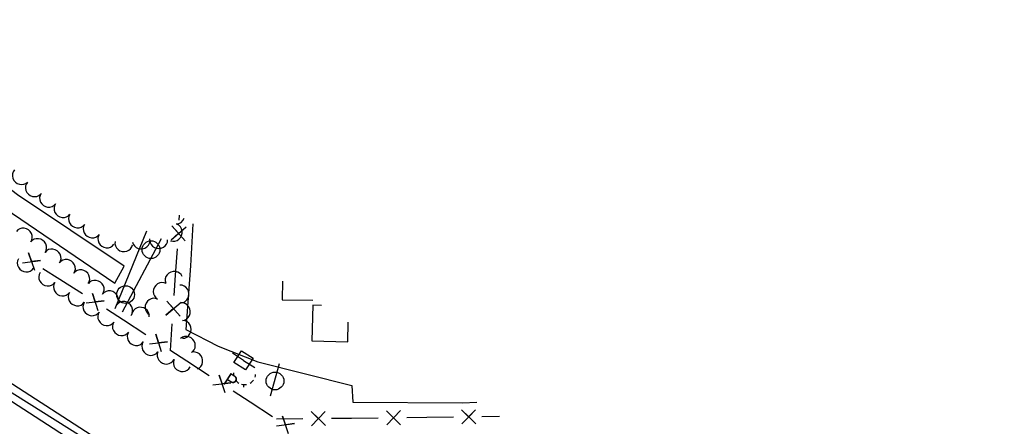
# Model space of a CAD drawing. Extents: x 1746010 to 1754829, y 655801 to 663091.
# Drawn here: x 1750940 to 1751497, y 659740 to 659969 of the extents above; entities that cross this region are included whole.
import ezdxf

# ---------------------------------------------------------------- set-up
doc = ezdxf.new("R2010")
doc.units = 0
for name, color, linetype in [('SURVEY - AERIAL SURVEY - Photo Control - Points - Elevations', 7, 'Continuous'), ('SURVEY - AERIAL SURVEY - Photo Control - Points - Locators', 7, 'Continuous'), ('SURVEY - AERIAL SURVEY - Photo Control with Text', 7, 'Continuous'), ('SURVEY - CENTERLINE - Existing Roads - Development', 7, 'Continuous'), ('SURVEY - CENTERLINE - Existing Roads Curve Text', 7, 'Continuous'), ('SURVEY - CENTERLINE - Existing Roads Text', 7, 'Continuous')]:
    doc.layers.add(name, color=color, linetype=linetype)

msp = doc.modelspace()

# ---------------------------------------------------------------- linework, layer by layer
at = {"layer": 'SURVEY - AERIAL SURVEY - Photo Control - Points - Elevations'}
msp.add_lwpolyline([(1751901.75, 659229.66), (1751903.78, 659232.49), (1751820.15, 659271.12), (1751720.09, 659319), (1751608.79, 659375.48), (1751511.86, 659425.67), (1751414.79, 659477.82), (1751309.42, 659535.79), (1751238.02, 659576.37), (1751119.98, 659647.33), (1751011.07, 659715.27), (1750920.63, 659773.68), (1750818.05, 659842.07), (1750688.97, 659930.51), (1750687.2, 659926.86)], dxfattribs=at)
at = {"layer": 'SURVEY - AERIAL SURVEY - Photo Control - Points - Locators'}
for points in [[(1751980.95, 659190.5), (1751865.03, 659241.97), (1751755.82, 659292.86), (1751627.46, 659356.04), (1751498.69, 659424), (1751376.94, 659489.68), (1751250.14, 659561.52), (1751113.15, 659643.48), (1750975.97, 659727.83), (1750858.05, 659804.33), (1750722.4, 659896.24), (1750620.83, 659969.19)], [(1750902.16, 659942.97), (1750902.94, 659927.48), (1750902.95, 659893.71), (1750903.13, 659886.46), (1750905.25, 659881.98), (1750918.24, 659872.14), (1750993.75, 659820.81), (1750998.91, 659830.33), (1750938.84, 659870.48), (1750930.13, 659877.33), (1750923.58, 659885.66), (1750919.37, 659891.98), (1750916.72, 659903.21), (1750915.86, 659929.32), (1750915.87, 659933.99)], [(1751981.66, 659195.26), (1751889.68, 659234.85), (1751784.21, 659284.64), (1751694.2, 659328.1), (1751603.81, 659373.71), (1751512.94, 659420.78), (1751440.06, 659459.77), (1751340.52, 659515.91), (1751224.32, 659581.45), (1751125.19, 659640.31), (1751025.2, 659702.76), (1750930.86, 659762.02), (1750841.47, 659821.93), (1750746.73, 659885.97), (1750687.69, 659926.53)], [(1751037.53, 659854.25), (1751036.18, 659830.51), (1751033.67, 659794.75), (1751051.88, 659785.39), (1751074.19, 659776.53), (1751127.1, 659763.15), (1751127.66, 659753.75), (1751189.3, 659753.39), (1751197.48, 659753.68)]]:
    msp.add_lwpolyline(points, dxfattribs=at)
at = {"layer": 'SURVEY - AERIAL SURVEY - Photo Control with Text'}
for p, q in [((1750993.85, 659806.48), (1751011.72, 659850.25)), ((1751019.81, 659845.72), (1750997.73, 659804.52)), ((1751014.04, 659839.62), (1751014.04, 659839.62)), ((1750999.74, 659814.36), (1750999.74, 659814.36)), ((1751081.35, 659757.27), (1751086.28, 659775.58)), ((1751083.84, 659765.66), (1751083.84, 659765.66))]:
    msp.add_line(p, q, dxfattribs=at)
for centre in [(1751014.03, 659839.66), (1750999.71, 659814.35), (1751083.83, 659765.69)]:
    msp.add_circle(centre, 5, dxfattribs=at)
at = {"layer": 'SURVEY - CENTERLINE - Existing Roads - Development'}
for points in [[(1751029.93, 659856.26), (1751030.12, 659859.11)], [(1751033.26, 659844.61), (1751025.8, 659853.03), (1751029.54, 659848.87), (1751025.28, 659845.15), (1751033.79, 659852.49)], [(1750941.66, 659832.31), (1750951.73, 659833.61), (1750946.74, 659832.93), (1750945.02, 659837.79), (1750948.36, 659828.13)], [(1751027.85, 659825.25), (1751028.85, 659840.2)], [(1750953.06, 659829.09), (1750962.73, 659823.06)], [(1751027.09, 659813.88), (1751027.85, 659825.25)], [(1750962.73, 659823.06), (1750966.88, 659820.47), (1750975.37, 659814.98)], [(1751087.97, 659821.87), (1751087.79, 659811.47), (1751105.12, 659811.19)], [(1750977.5, 659809.67), (1750987.68, 659810.76), (1750982.63, 659810.19), (1750981.04, 659815.05), (1750984.14, 659805.38)], [(1751030.42, 659802.24), (1751022.96, 659810.65), (1751026.69, 659806.5), (1751022.43, 659802.78), (1751030.95, 659810.12)], [(1751109.94, 659808.19), (1751105.18, 659808.34), (1751104.56, 659788.3), (1751124.75, 659787.67), (1751125.1, 659798.75)], [(1750988.89, 659806.24), (1750998.46, 659800.05)], [(1750998.46, 659800.05), (1751011.06, 659791.9)], [(1751025.01, 659782.88), (1751026.01, 659797.83)], [(1751013.19, 659786.59), (1751023.36, 659787.68), (1751018.32, 659787.11), (1751016.73, 659791.97), (1751019.82, 659782.3)], [(1751024.58, 659783.16), (1751034.15, 659776.96)], [(1751034.15, 659776.96), (1751046.75, 659768.82)], [(1751048.88, 659763.51), (1751059.05, 659764.6), (1751054.01, 659764.03), (1751052.42, 659768.89), (1751055.51, 659759.22)], [(1751060.26, 659760.08), (1751069.83, 659753.88)], [(1751069.83, 659753.88), (1751082.43, 659745.74)], [(1751104.35, 659740.48), (1751112.04, 659748.51), (1751108.25, 659744.49), (1751104.17, 659748.42), (1751112.22, 659740.57)], [(1751146.7, 659740.97), (1751154.39, 659749), (1751150.6, 659744.99), (1751146.52, 659748.91), (1751154.57, 659741.06)], [(1751189.05, 659741.47), (1751196.74, 659749.5), (1751192.94, 659745.48), (1751188.87, 659749.41), (1751196.92, 659741.56)], [(1751084.61, 659740.37), (1751094.73, 659741.64), (1751089.72, 659740.98), (1751088.03, 659745.82), (1751091.32, 659736.19)], [(1751084.63, 659744.32), (1751099.58, 659744.49)], [(1751115.62, 659744.68), (1751126.98, 659744.81)], [(1751126.98, 659744.81), (1751141.92, 659744.98)], [(1751157.97, 659745.17), (1751169.33, 659745.31)], [(1751169.33, 659745.31), (1751184.27, 659745.48)], [(1751200.32, 659745.67), (1751210.16, 659745.78)]]:
    msp.add_lwpolyline(points, dxfattribs=at)
at = {"layer": 'SURVEY - CENTERLINE - Existing Roads Curve Text'}
for p, q in [((1751066.11, 659777.31), (1751059.81, 659781.38)), ((1751066.11, 659777.31), (1751072.41, 659773.24)), ((1751066.21, 659762.26), (1751066.31, 659763.66))]:
    msp.add_line(p, q, dxfattribs=at)
msp.add_lwpolyline([(1751064.95, 659782.7), (1751071.5, 659778.47), (1751067.27, 659771.92), (1751060.71, 659776.15)], close=True, dxfattribs=at)
for start, end in [(175.9869, 190.6078), (341.1735, 355.0629), (217.8648, 238.2073), (253.5079, 280.0232), (299.5497, 324.3197)]:
    msp.add_arc((1751066.7, 659769.85), 6.25, start, end, dxfattribs=at)
at = {"layer": 'SURVEY - CENTERLINE - Existing Roads Text'}
for centre, major_axis, end_param in [((1750940.89, 659881.17), (-3.67, 3.4), 3.141593), ((1750948.22, 659874.37), (-3.67, 3.4), 3.141593), ((1750956.19, 659868.35), (-4.06, 2.92), 3.141593), ((1750964.32, 659862.52), (-4.06, 2.92), 3.141593), ((1750972.47, 659856.74), (-4.13, 2.81), 3.141593), ((1750942.28, 659846.97), (4.05, -2.94), 3.141593), ((1750980.74, 659851.11), (-4.13, 2.81), 3.141593), ((1751026.86, 659849.35), (-1.79, -4.67), 3.141593), ((1751028.27, 659859.16), (-0.06, -5), 1.229637), ((1750950.38, 659841.09), (4.05, -2.94), 3.141593), ((1750989.01, 659845.49), (-4.13, 2.81), 3.141593), ((1750998.68, 659843.31), (-4.91, 0.94), 3.141593), ((1751008.5, 659844.82), (-4.92, -0.87), 3.141593), ((1751018.4, 659845.08), (-5, -0.11), 3.141593), ((1750958.47, 659835.22), (4.05, -2.94), 3.141593), ((1750943.64, 659831.89), (-4.25, 2.63), 3.141593), ((1750966.57, 659829.35), (4.05, -2.94), 3.141593), ((1750955.73, 659823.98), (-4.15, 2.79), 3.141593), ((1750974.66, 659823.47), (4.05, -2.94), 3.141593), ((1751026.94, 659822.69), (4.66, 1.82), 3.141593), ((1750964.03, 659818.4), (-4.15, 2.79), 3.141593), ((1750982.75, 659817.59), (4.01, -2.99), 3.141593), ((1751020.1, 659816.21), (2.44, 4.36), 3.141593), ((1751030.66, 659814.7), (0.36, -4.99), 3.141593), ((1750972.33, 659812.82), (-4.15, 2.79), 3.141593), ((1750990.77, 659811.62), (4.01, -2.99), 3.141593), ((1751015.45, 659807.37), (2.26, 4.46), 3.141593), ((1750980.62, 659807.23), (-4.15, 2.79), 3.141593), ((1750998.79, 659805.65), (4.01, -2.99), 3.141593), ((1751008.1, 659802.51), (4.96, -0.65), 3.141593), ((1751031.38, 659804.72), (0.36, -4.99), 3.141593), ((1750988.92, 659801.65), (-4.15, 2.79), 3.141593), ((1750997.21, 659796.07), (-4.15, 2.79), 3.141593), ((1751031.88, 659794.75), (-0.11, -5), 3.141593), ((1751005.51, 659790.49), (-4.15, 2.79), 3.141593), ((1751034.12, 659785.93), (3.42, -3.65), 3.141593), ((1751013.8, 659784.9), (-4.15, 2.79), 3.141593), ((1751022.47, 659779.99), (-4.53, 2.12), 3.141593), ((1751038.36, 659777.1), (1.82, -4.66), 3.141593), ((1751031.52, 659775.76), (-4.53, 2.12), 3.141593)]:
    msp.add_ellipse(centre, major_axis=major_axis, ratio=0.940188, start_param=0, end_param=end_param, dxfattribs=at)

# ---------------------------------------------------------------- texts
at = {"layer": 'SURVEY - CENTERLINE - Existing Roads Curve Text'}
msp.add_text('P', height=7.48, rotation=327.1404, dxfattribs=at).set_placement((1751054.11, 659764.46))

doc.saveas('drawing.dxf')
